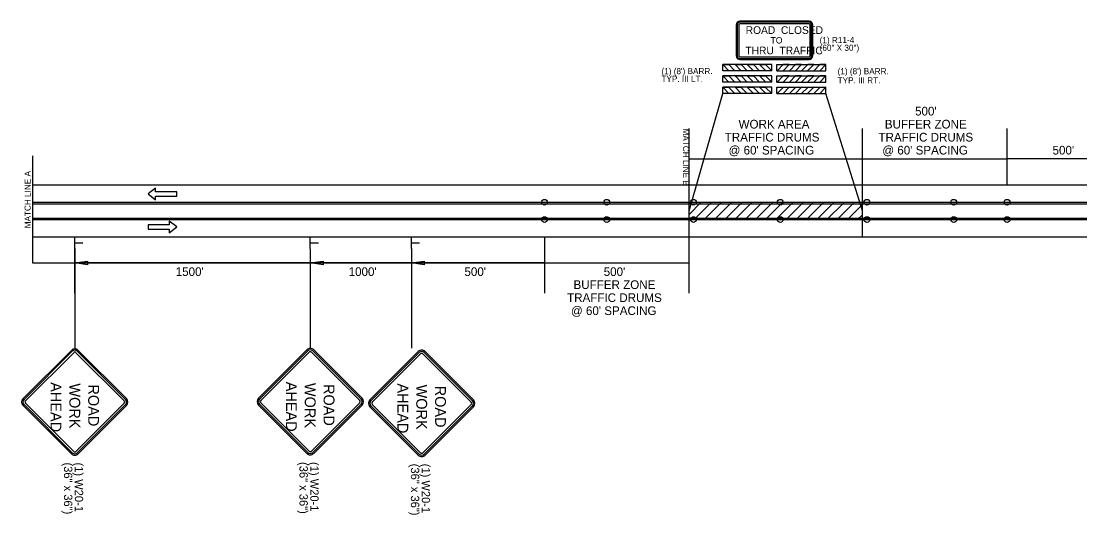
# Model space of a CAD drawing. Extents: x 1930579 to 1946213, y 596452 to 597784.
# Drawn here: x 1938464 to 1939196, y 596685 to 597027 of the extents above; entities that cross this region are included whole.
import ezdxf

# ---------------------------------------------------------------- set-up
doc = ezdxf.new("R2010")
doc.units = 0
for name, color, linetype in [('Default', 7, 'Continuous'), ('Level 3', 7, 'Continuous'), ('P_TC_Signs_Permanent', 7, 'Continuous'), ('P_TC_Signs_Temporary', 7, 'Continuous'), ('R_Border', 7, 'Continuous'), ('R_Striping', 7, 'Continuous')]:
    doc.layers.add(name, color=color, linetype=linetype)

# ---------------------------------------------------------------- blocks, each defined once
blk = doc.blocks.new('W20-1')
at = {"layer": 'P_TC_Signs_Temporary'}
for p, q in [((-5.97, 6.53), (-0.4, 12.1)), ((-5.86, 6.42), (-0.29, 11.99)), ((-5.7, 6.26), (-0.13, 11.83)), ((0.13, 11.83), (5.7, 6.26)), ((0.29, 11.99), (5.86, 6.42)), ((0.4, 12.1), (5.97, 6.53)), ((-0.4, 0.16), (-5.97, 5.73)), ((-0.29, 0.28), (-5.86, 5.84)), ((-0.13, 0.43), (-5.7, 6)), ((5.7, 6), (0.13, 0.43)), ((5.86, 5.84), (0.29, 0.28)), ((5.97, 5.73), (0.4, 0.16))]:
    blk.add_line(p, q, dxfattribs=at)
for centre, radius, start, end in [((0, 11.7), 0.562, 45, 135), ((0, 11.7), 0.406, 45, 135), ((0, 11.7), 0.188, 45, 135), ((-5.57, 6.13), 0.562, 135, 225), ((-5.57, 6.13), 0.406, 135, 225), ((-5.57, 6.13), 0.187, 135, 225), ((5.57, 6.13), 0.187, 315, 45), ((5.57, 6.13), 0.406, 315, 45), ((5.57, 6.13), 0.562, 315, 45), ((0, 0.56), 0.562, 225, 315), ((0, 0.56), 0.406, 225, 315), ((0, 0.56), 0.188, 225, 315)]:
    blk.add_arc(centre, radius, start, end, dxfattribs=at)
for s, p in [(' ROAD ', (-2.5, 7.67)), ('WORK', (-2.16, 5.5)), (' AHEAD ', (-2.76, 3.33))]:
    blk.add_text(s, height=1.25, dxfattribs=at).set_placement(p)
blk = doc.blocks.new('R11-4')
at = {"layer": 'P_TC_Signs_Permanent'}
for p, q in [((-7.5, 6.8), (-7.5, 0.7)), ((-7.3, 6.8), (-7.3, 0.7)), ((-7, 6.8), (-7, 0.7)), ((6.8, 7.5), (-6.8, 7.5)), ((6.8, 7.3), (-6.8, 7.3)), ((6.8, 7), (-6.8, 7)), ((7, 0.7), (7, 6.8)), ((7.3, 0.7), (7.3, 6.8)), ((7.5, 0.7), (7.5, 6.8)), ((-6.8, 0.5), (6.8, 0.5)), ((-6.8, 0.2), (6.8, 0.2)), ((-6.8, 0), (6.8, 0))]:
    blk.add_line(p, q, dxfattribs=at)
for centre, radius, start, end in [((-6.8, 6.8), 0.7, 90, 180), ((-6.8, 6.8), 0.5, 90, 180), ((-6.8, 6.8), 0.2, 90, 180), ((6.8, 6.8), 0.7, 0, 90), ((6.8, 6.8), 0.5, 0, 90), ((6.8, 6.8), 0.2, 0, 90), ((-6.8, 0.7), 0.7, 180, 270), ((-6.8, 0.7), 0.5, 180, 270), ((-6.8, 0.7), 0.2, 180, 270), ((6.8, 0.7), 0.7, 270, 0), ((6.8, 0.7), 0.5, 270, 0), ((6.8, 0.7), 0.2, 270, 0)]:
    blk.add_arc(centre, radius, start, end, dxfattribs=at)
for s, height, p in [('ROAD  CLOSED', 1.5, (-5.63, 5)), ('TO', 1.25, (-0.75, 3.12)), ('THRU  TRAFFIC', 1.5, (-5.69, 1))]:
    blk.add_text(s, height=height, dxfattribs=at).set_placement(p)

msp = doc.modelspace()

# ---------------------------------------------------------------- linework, layer by layer
at = {"layer": 'Default'}
for p, q in [((1938926.05, 596877.33), (1938926.05, 596952.33)), ((1939046.05, 596877.33), (1939046.05, 596952.33)), ((1939146.05, 596913.33), (1939146.05, 596952.33)), ((1938471.95, 596933.41), (1938471.95, 596859.3)), ((1938926.05, 596931.37), (1939146.05, 596931.37)), ((1939500.15, 596931.37), (1939146.05, 596931.37)), ((1938471.95, 596913.33), (1939500.15, 596913.33)), ((1938471.95, 596913.33), (1938471.95, 596859.3)), ((1938926.05, 596838.33), (1938926.05, 596913.33)), ((1938471.95, 596901.33), (1939500.15, 596901.33)), ((1938471.95, 596900.33), (1939500.15, 596900.33)), ((1938926.05, 596900), (1938927.38, 596901.33)), ((1938926.05, 596892.93), (1938934.45, 596901.33)), ((1938929.53, 596889.33), (1938941.53, 596901.33)), ((1938936.6, 596889.33), (1938948.6, 596901.33)), ((1938943.67, 596889.33), (1938955.67, 596901.33)), ((1938950.74, 596889.33), (1938962.74, 596901.33)), ((1938957.81, 596889.33), (1938969.81, 596901.33)), ((1938964.88, 596889.33), (1938976.88, 596901.33)), ((1938971.95, 596889.33), (1938983.95, 596901.33)), ((1938979.02, 596889.33), (1938991.02, 596901.33)), ((1938986.09, 596889.33), (1938998.09, 596901.33)), ((1938993.17, 596889.33), (1939005.17, 596901.33)), ((1939000.24, 596889.33), (1939012.24, 596901.33)), ((1939007.31, 596889.33), (1939019.31, 596901.33)), ((1939014.38, 596889.33), (1939026.38, 596901.33)), ((1939021.45, 596889.33), (1939033.16, 596901.04)), ((1939028.52, 596889.33), (1939040.52, 596901.33)), ((1939035.59, 596889.33), (1939046.05, 596899.79)), ((1938471.95, 596890.33), (1939500.15, 596890.33)), ((1938471.95, 596889.33), (1939500.15, 596889.33)), ((1939042.66, 596889.33), (1939046.05, 596892.72)), ((1938471.95, 596877.33), (1939500.15, 596877.33)), ((1938501.16, 596838.33), (1938501.16, 596877.33)), ((1938501.16, 596869.35), (1938501.16, 596877.33)), ((1938501.28, 596873.32), (1938506.73, 596873.32)), ((1938664.05, 596869.35), (1938664.05, 596877.33)), ((1938664.17, 596873.32), (1938669.62, 596873.32)), ((1938734.05, 596869.35), (1938734.05, 596877.33)), ((1938734.17, 596873.32), (1938739.62, 596873.32)), ((1938826.05, 596877.33), (1938826.05, 596838.33)), ((1938471.95, 596859.3), (1938826.05, 596859.3)), ((1938501.15, 596859.3), (1938510.02, 596860.63)), ((1938510.02, 596857.97), (1938501.15, 596859.3)), ((1938826.05, 596859.3), (1938501.16, 596859.3)), ((1938510.02, 596860.63), (1938510.02, 596857.97)), ((1938664.05, 596859.3), (1938672.91, 596860.63)), ((1938672.91, 596857.97), (1938664.05, 596859.3)), ((1938672.91, 596860.63), (1938672.91, 596857.97)), ((1938734.05, 596859.3), (1938742.91, 596860.63)), ((1938742.91, 596857.97), (1938734.05, 596859.3)), ((1938742.91, 596860.63), (1938742.91, 596857.97)), ((1938826.05, 596859.3), (1938926.05, 596859.3))]:
    msp.add_line(p, q, dxfattribs=at)
for centre in [(1938826.05, 596901.33), (1938869.15, 596901.33), (1938929.15, 596901.33), (1938989.15, 596901.33), (1939049.15, 596901.33), (1939109.15, 596901.33), (1939146.05, 596901.33), (1938826.05, 596889.33), (1938869.15, 596889.33), (1938929.15, 596889.33), (1938989.15, 596889.33), (1939049.15, 596889.33), (1939109.15, 596889.33), (1939146.05, 596889.33)]:
    msp.add_circle(centre, 1.99, dxfattribs=at)
at = {"layer": 'Level 3'}
for p, q in [((1938983.35, 596996.63), (1938949.45, 596996.63)), ((1938949.45, 596992.37), (1938949.45, 596996.63)), ((1938949.48, 596992.38), (1938949.45, 596992.41)), ((1938983.35, 596992.37), (1938949.45, 596992.37)), ((1938983.35, 596992.37), (1938983.35, 596996.63)), ((1938986.91, 596996.63), (1939020.81, 596996.63)), ((1938986.91, 596992.37), (1938986.91, 596996.63)), ((1938986.91, 596992.37), (1939020.81, 596992.37)), ((1939020.78, 596992.38), (1939020.81, 596992.41)), ((1939020.81, 596992.37), (1939020.81, 596996.63)), ((1938983.35, 596988.73), (1938949.45, 596988.73)), ((1938949.45, 596984.49), (1938949.45, 596988.73)), ((1938949.45, 596984.49), (1938949.45, 596988.73)), ((1938983.35, 596984.49), (1938949.45, 596984.49)), ((1938983.35, 596984.49), (1938983.35, 596988.73)), ((1938986.91, 596988.73), (1939020.81, 596988.73)), ((1938986.91, 596984.49), (1938986.91, 596988.73)), ((1938986.91, 596984.49), (1939020.81, 596984.49)), ((1939020.81, 596984.49), (1939020.81, 596988.73)), ((1939020.81, 596984.49), (1939020.81, 596988.73)), ((1938983.35, 596980.87), (1938949.45, 596980.87)), ((1938949.45, 596976.63), (1938949.45, 596980.87)), ((1938983.35, 596976.63), (1938949.45, 596976.63)), ((1938983.35, 596976.63), (1938983.35, 596980.87)), ((1938986.91, 596980.87), (1939020.81, 596980.87)), ((1938986.91, 596976.63), (1938986.91, 596980.87)), ((1938986.91, 596976.63), (1939020.81, 596976.63)), ((1939020.81, 596976.63), (1939020.81, 596980.87))]:
    msp.add_line(p, q, dxfattribs=at)
for points in [[(1938949.45, 596996.63), (1938953.62, 596996.61), (1938957.85, 596992.38), (1938953.7, 596992.38)], [(1938957.92, 596996.63), (1938962.09, 596996.61), (1938966.32, 596992.38), (1938962.17, 596992.38)], [(1938966.39, 596996.63), (1938970.56, 596996.61), (1938974.79, 596992.38), (1938970.64, 596992.38)], [(1938974.86, 596996.63), (1938979.03, 596996.61), (1938983.26, 596992.38), (1938979.11, 596992.38)], [(1938995.4, 596996.63), (1938991.23, 596996.61), (1938987, 596992.38), (1938991.15, 596992.38)], [(1939003.87, 596996.63), (1938999.7, 596996.61), (1938995.47, 596992.38), (1938999.62, 596992.38)], [(1939012.34, 596996.63), (1939008.17, 596996.61), (1939003.94, 596992.38), (1939008.09, 596992.38)], [(1939020.81, 596996.63), (1939016.64, 596996.61), (1939012.41, 596992.38), (1939016.56, 596992.38)], [(1938949.45, 596988.73), (1938953.62, 596988.72), (1938957.85, 596984.49), (1938953.7, 596984.49)], [(1938957.92, 596988.73), (1938962.09, 596988.72), (1938966.32, 596984.49), (1938962.17, 596984.49)], [(1938966.39, 596988.73), (1938970.56, 596988.72), (1938974.79, 596984.49), (1938970.64, 596984.49)], [(1938974.86, 596988.73), (1938979.03, 596988.72), (1938983.26, 596984.49), (1938979.11, 596984.49)], [(1938995.4, 596988.73), (1938991.23, 596988.72), (1938987, 596984.49), (1938991.15, 596984.49)], [(1939003.87, 596988.73), (1938999.7, 596988.72), (1938995.47, 596984.49), (1938999.62, 596984.49)], [(1939012.34, 596988.73), (1939008.17, 596988.72), (1939003.94, 596984.49), (1939008.09, 596984.49)], [(1939020.81, 596988.73), (1939016.64, 596988.72), (1939012.41, 596984.49), (1939016.56, 596984.49)], [(1938949.45, 596980.87), (1938953.62, 596980.86), (1938957.85, 596976.63), (1938953.7, 596976.63)], [(1938957.92, 596980.87), (1938962.09, 596980.86), (1938966.32, 596976.63), (1938962.17, 596976.63)], [(1938966.39, 596980.87), (1938970.56, 596980.86), (1938974.79, 596976.63), (1938970.64, 596976.63)], [(1938974.86, 596980.87), (1938979.03, 596980.86), (1938983.26, 596976.63), (1938979.11, 596976.63)], [(1938995.4, 596980.87), (1938991.23, 596980.86), (1938987, 596976.63), (1938991.15, 596976.63)], [(1939003.87, 596980.87), (1938999.7, 596980.86), (1938995.47, 596976.63), (1938999.62, 596976.63)], [(1939012.34, 596980.87), (1939008.17, 596980.86), (1939003.94, 596976.63), (1939008.09, 596976.63)], [(1939020.81, 596980.87), (1939016.64, 596980.86), (1939012.41, 596976.63), (1939016.56, 596976.63)]]:
    msp.add_lwpolyline(points, close=True, dxfattribs=at)
at = {"layer": 'R_Border'}
for p, q in [((1938926.05, 596895.33), (1938949.45, 596976.63)), ((1939046.05, 596895.33), (1939020.81, 596976.63)), ((1938501.16, 596869.35), (1938501.15, 596799.81)), ((1938664.05, 596869.17), (1938664.04, 596800.13)), ((1938734.05, 596869.35), (1938734.04, 596800.32))]:
    msp.add_line(p, q, dxfattribs=at)
at = {"layer": 'R_Striping'}
for points in [[(1938557, 596911.05), (1938551.81, 596907.05), (1938557, 596903.05), (1938557, 596905.55), (1938571.71, 596905.55), (1938571.71, 596908.55), (1938557, 596908.55)], [(1938566.52, 596880.24), (1938571.71, 596884.24), (1938566.52, 596888.24), (1938566.52, 596885.74), (1938551.81, 596885.74), (1938551.81, 596882.74), (1938566.52, 596882.74)]]:
    msp.add_lwpolyline(points, close=True, dxfattribs=at)

# ---------------------------------------------------------------- block references
at = {"layer": 'Default', "xscale": 6, "yscale": 6, "rotation": -90.00000000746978}
for p in [(1938464.36, 596763.02), (1938627.25, 596763.35), (1938704.36, 596762.18)]:
    msp.add_blockref('W20-1', p, dxfattribs=at)
at = {"layer": 'R_Border', "xscale": 3.529411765, "yscale": 3.529411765}
msp.add_blockref('R11-4', (1938985.13, 597000.18), dxfattribs=at)

# ---------------------------------------------------------------- texts
at = {"layer": 'Default'}
for s, p in [("500' ", (1939082.43, 596961.37)), ('WORK AREA', (1938960.33, 596952.37)), ('BUFFER ZONE', (1939061.54, 596952.37)), ('TRAFFIC DRUMS ', (1938950.76, 596943.37)), ('TRAFFIC DRUMS ', (1939057.1, 596943.37)), ("@ 60' SPACING", (1938953.43, 596934.37)), ("@ 60' SPACING", (1939059.77, 596934.37)), ("500'", (1938867.03, 596850.3)), ('BUFFER ZONE', (1938846.15, 596841.3)), ('TRAFFIC DRUMS ', (1938841.71, 596832.3)), ("@ 60' SPACING", (1938844.38, 596823.3))]:
    msp.add_text(s, height=6, dxfattribs=at).set_placement(p)
for s, height, rotation, p in [('MATCH LINE B', 4.2353, 270, (1938921.82, 596952.33)), ("500'", 6, 360, (1939177.55, 596934.37)), ('MATCH LINE A', 4.2353, 90, (1938470.6, 596883.3)), ("1500'", 6, 360, (1938570.93, 596850.3)), ("1000'", 6, 360, (1938690.57, 596850.3)), ("500'", 6, 360, (1938770.69, 596850.3))]:
    msp.add_text(s, height=height, rotation=rotation, dxfattribs=at).set_placement(p)
at = {"layer": 'R_Border'}
for s, height, rotation, p in [('(1) R11-4', 4.235, 0.17192, (1939016.43, 597011.41)), ('(60" X 30")', 4.2353, 0.17192, (1939016.44, 597006.1)), ("(1) (8') BARR.", 4.2353, 0.17192, (1938906.98, 596989.92)), ("(1) (8') BARR.", 4.2353, 360, (1939028.86, 596989.92)), ('TYP. III LT.', 4.2353, 0.17192, (1938907, 596984.61)), ('TYP. III RT.', 4.2353, 360, (1939028.86, 596983.56)), ('(36" x 36")', 5.76, 270, (1938493.66, 596721.24)), ('(1) W20-1', 5.76, 270, (1938501.15, 596721.24)), ('(36" x 36")', 5.76, 270, (1938656.55, 596721.56)), ('(1) W20-1', 5.76, 270, (1938664.04, 596721.56)), ('(36" x 36")', 5.76, 270, (1938733.66, 596720.4)), ('(1) W20-1', 5.76, 270, (1938741.15, 596720.4))]:
    msp.add_text(s, height=height, rotation=rotation, dxfattribs=at).set_placement(p)

doc.saveas('drawing.dxf')
